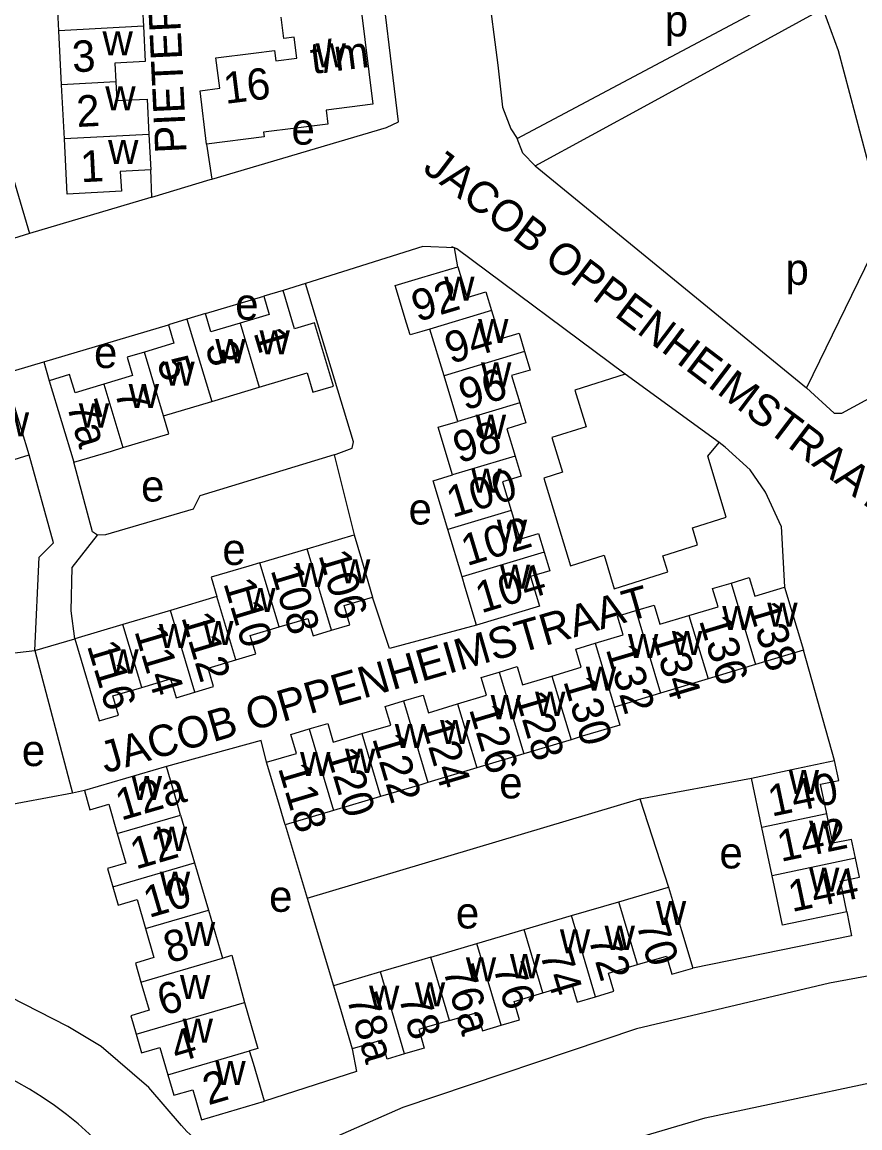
# Model space of a CAD drawing. Extents: x 157569 to 159501, y 382907 to 384670.
# Drawn here: x 158949.1 to 159055.8, y 383261.5 to 383402.3 of the extents above; entities that cross this region are included whole.
import ezdxf

# ---------------------------------------------------------------- set-up
doc = ezdxf.new("R2010")
doc.units = 0
for name, color, linetype in [('BLT_Basislijn', 7, 'Continuous'), ('BLT_Bebouwing', 7, 'Continuous'), ('BLT_Centroide', 7, 'Continuous'), ('BLT_Huisnummer', 7, 'Continuous'), ('BLT_Huisnummer_ tussenligend', 7, 'Continuous'), ('BLT_Huisnummer_reeks', 7, 'Continuous'), ('BLT_Onderverdeling_panden', 7, 'Continuous'), ('BLT_Straatnaam_verkleind', 7, 'Continuous')]:
    doc.layers.add(name, color=color, linetype=linetype)

msp = doc.modelspace()

# ---------------------------------------------------------------- linework, layer by layer
at = {"layer": 'BLT_Basislijn'}
for p, q in [((159014.42, 383384.03), (159028.76, 383391.86)), ((158972.61, 383386.8), (158973.27, 383382.34)), ((159014.42, 383384.03), (159049, 383355.73)), ((158965.65, 383380.05), (158965.49, 383383.53)), ((158950.05, 383375.4), (158944.99, 383373.86)), ((159004.61, 383371.17), (159004.15, 383373.58)), ((158985.21, 383369.05), (158982.34, 383368.14)), ((158972.45, 383365.2), (158979.89, 383367.41)), ((158951.86, 383359.07), (158967.74, 383363.79)), ((158946.3, 383357.42), (158951.86, 383359.07)), ((158951.86, 383359.07), (158952.57, 383356.65)), ((159037.86, 383348.77), (159025.91, 383357.49)), ((158988.85, 383347.23), (158991.38, 383337.03)), ((159045.74, 383338.12), (159046.18, 383330.34)), ((158950.73, 383322.27), (158955.82, 383323.75)), ((158947.42, 383321.92), (158950.73, 383322.27)), ((158950.73, 383322.27), (158955.52, 383304.09)), ((159052.56, 383308.26), (159048.59, 383322.32)), ((159027.77, 383303.39), (159041.99, 383306.03)), ((158955.52, 383304.09), (158943.57, 383301.89)), ((158957.04, 383304.44), (158955.52, 383304.09)), ((158985.41, 383290.74), (159027.77, 383303.39)), ((159027.77, 383303.39), (159031.43, 383292.15)), ((158982.62, 383300.07), (158985.41, 383290.74)), ((158985.41, 383290.74), (158988.75, 383279.57))]:
    msp.add_line(p, q, dxfattribs=at)
for points in [[(158941.85, 383428.43), (158943.35, 383398.06), (158950.05, 383375.4)], [(159012.14, 383387.53), (159050.09, 383407.72), (159049.75, 383410.1), (159047.73, 383417.9), (159045.92, 383423.74)], [(158973.27, 383382.34), (158995.52, 383388.93), (158997.04, 383389.62), (158994.36, 383411.78)], [(159007.74, 383411.49), (159008.38, 383407.02), (159009.67, 383396.84), (159010.29, 383391.5), (159011.35, 383388.75), (159012.14, 383387.53)], [(159028.76, 383391.86), (159050.35, 383403.64), (159051.14, 383403.8), (159053, 383398.73), (159058.78, 383376.99), (159058.82, 383375.95), (159049, 383355.73)], [(159014.42, 383384.03), (159012.86, 383385.63), (159012.14, 383387.53)], [(158965.65, 383380.05), (158973.07, 383382.28), (158973.27, 383382.34)], [(158965.65, 383380.05), (158965.49, 383380), (158950.05, 383375.4)], [(159004.15, 383373.58), (159000.13, 383373.74), (158985.21, 383369.05)], [(159004.15, 383373.58), (159003.82, 383373.72)], [(159025.91, 383357.49), (159004.47, 383373.44), (159004.15, 383373.58)], [(158988.85, 383347.23), (158989.12, 383347.31), (158991.13, 383348.05), (158991.29, 383348.85), (158985.21, 383369.05)], [(159025.91, 383357.49), (159019.49, 383355.46), (159020.91, 383350.8), (159016.56, 383349.42), (159017.9, 383345), (159015.54, 383344.25), (159018.93, 383333.08), (159023.2, 383334.43), (159024.5, 383330.15), (159031.32, 383332.31), (159030.7, 383334.35), (159035.12, 383335.75), (159034.47, 383337.91), (159038.77, 383339.27), (159036.41, 383347.04), (159037.86, 383348.77)], [(159049, 383355.73), (159052.52, 383352.54), (159053.48, 383352.51), (159057.95, 383354.93)], [(158983.24, 383235.61), (158982.98, 383236.31), (158981.28, 383239.26), (158981.31, 383241.77), (158983.04, 383243.59), (159007.41, 383254.28), (159036.07, 383262.73), (159100, 383276.35), (159146.03, 383286.21), (159155.39, 383288.52), (159181.52, 383295.52), (159205.36, 383303.77), (159241.92, 383319.57), (159301.34, 383349.43)], [(159045.74, 383338.12), (159043.77, 383342.46), (159041.82, 383345.29), (159038.64, 383348.2), (159037.86, 383348.77)], [(158950.73, 383322.27), (158951.29, 383334.17), (158953.11, 383336.02), (158950.02, 383347.21)], [(158988.85, 383347.23), (158971.76, 383341.99), (158970.9, 383340.27), (158959.73, 383337.01), (158958.71, 383336.98)], [(158958.71, 383336.98), (158958.09, 383337.42), (158955.69, 383346.26)], [(159258.99, 383340.92), (159227.33, 383325.46), (159190.02, 383310.81), (159165.47, 383303.18), (159141.61, 383297.45), (159119.64, 383292.64), (159100, 383288.81), (159051.92, 383279.92), (159027.35, 383274.07), (158997.57, 383264.08), (158986.46, 383259.17)], [(158955.82, 383323.75), (158955.38, 383327.35), (158955.47, 383332.86), (158958.71, 383336.98)], [(159006.98, 383325.53), (158995.91, 383322.55), (158993.74, 383329.1)], [(158980.25, 383308.06), (158979.54, 383310.8), (158967.49, 383307.49)], [(159054.12, 383289), (159054.7, 383285.92), (159034.49, 383281.82)], [(158969.39, 383261.76), (158965.23, 383266.61), (158959.2, 383271.82), (158954.92, 383274.37), (158947.54, 383278.14), (158941.39, 383279.86), (158939.55, 383280.38)], [(158962.81, 383255.07), (158961.61, 383256.56), (158960.36, 383257.99), (158959.05, 383259.37), (158957.67, 383260.7), (158956.25, 383261.97), (158954.77, 383263.17), (158953.24, 383264.32), (158951.67, 383265.39), (158950.06, 383266.4), (158948.4, 383267.35), (158946.7, 383268.22), (158944.97, 383269.02), (158943.21, 383269.74), (158941.42, 383270.4), (158939.6, 383270.97), (158938.1, 383271.39)], [(158991.13, 383271.52), (158991.68, 383268.66), (158979.96, 383264.86)], [(158969.39, 383261.76), (158970.1, 383261.01), (158970.86, 383260.32), (158971.67, 383259.69), (158972.53, 383259.13), (158973.43, 383258.63), (158974.37, 383258.21), (158975.34, 383257.86), (158976.33, 383257.59), (158977.34, 383257.39), (158978.36, 383257.27), (158979.39, 383257.24), (158980.41, 383257.28), (158981.43, 383257.4), (158982.44, 383257.6), (158983.43, 383257.88), (158984.48, 383258.27)]]:
    msp.add_lwpolyline(points, dxfattribs=at)
at = {"layer": 'BLT_Bebouwing'}
for p, q in [((158953.79, 383401.25), (158953.43, 383408.13)), ((158992.23, 383404.25), (158992.74, 383400.13)), ((158954.15, 383394.37), (158953.79, 383401.25)), ((158992.74, 383400.13), (158993.25, 383396)), ((158954.5, 383387.48), (158954.15, 383394.37)), ((158965.26, 383388.03), (158965.49, 383383.53)), ((158983.95, 383388.83), (158979.84, 383388.32)), ((158982.34, 383368.14), (158979.89, 383367.41)), ((158970.1, 383364.49), (158967.74, 383363.79)), ((158972.45, 383365.2), (158970.1, 383364.49)), ((159002.83, 383357.27), (159001.02, 383363.24)), ((159004.57, 383351.47), (159002.83, 383357.27)), ((158952.57, 383356.65), (158955.69, 383346.26)), ((158973.25, 383354.01), (158979.31, 383355.83)), ((158950.02, 383347.21), (158948.08, 383353.68)), ((158967.12, 383352.17), (158973.25, 383354.01)), ((159005.14, 383331.65), (159003.32, 383337.69)), ((158985.4, 383335.25), (158991.38, 383337.03)), ((158979.4, 383333.46), (158985.4, 383335.25)), ((159046.18, 383330.34), (159048.59, 383322.32)), ((158973.92, 383329.15), (158968, 383327.39)), ((158968, 383327.39), (158961.95, 383325.58)), ((158961.95, 383325.58), (158955.82, 383323.75)), ((159048.59, 383322.32), (159042.49, 383320.49)), ((159042.49, 383320.49), (159036.45, 383318.67)), ((159036.45, 383318.67), (159030.4, 383316.85)), ((159030.4, 383316.85), (159024.53, 383315.08)), ((159019.01, 383310.92), (159012.98, 383309.11)), ((159012.98, 383309.11), (159007, 383307.32)), ((158967.49, 383307.49), (158957.04, 383304.44)), ((159007, 383307.32), (159000.76, 383305.45)), ((159043.31, 383299.74), (159041.99, 383306.03)), ((158994.76, 383303.67), (158988.76, 383301.89)), ((158969.3, 383301.31), (158971.08, 383295.22)), ((158988.76, 383301.89), (158982.62, 383300.07)), ((159044.61, 383293.59), (159043.31, 383299.74)), ((158971.08, 383295.22), (158972.84, 383289.19)), ((159025.09, 383290.28), (159031.43, 383292.15)), ((159019.06, 383288.51), (159025.09, 383290.28)), ((158972.84, 383289.19), (158974.63, 383283.07)), ((159013.04, 383286.73), (159019.06, 383288.51)), ((159007, 383284.95), (159013.04, 383286.73)), ((159001.14, 383283.22), (159007, 383284.95)), ((158994.73, 383281.33), (158988.75, 383279.57)), ((158967.68, 383268.24), (158968.44, 383265.62)), ((158971.94, 383262.51), (158979.96, 383264.86))]:
    msp.add_line(p, q, dxfattribs=at)
for points in [[(158960.3, 383408.49), (158960.43, 383406.08), (158964.32, 383406.29), (158964.55, 383401.81)], [(158978.59, 383398.39), (158981.24, 383398.72), (158981.4, 383397.41), (158984.1, 383397.75), (158983.77, 383400.41), (158982.42, 383400.24), (158982.08, 383402.99)], [(158964.55, 383401.81), (158964.78, 383397.33), (158960.92, 383397.13), (158961.04, 383394.73)], [(158972.61, 383386.8), (158971.77, 383393.6), (158974.27, 383393.91), (158973.79, 383397.79), (158978.59, 383398.39)], [(158993.25, 383396), (158993.76, 383391.88), (158987.83, 383391.14)], [(158961.04, 383394.73), (158961.17, 383392.34), (158965.02, 383392.54), (158965.26, 383388.03)], [(158987.83, 383391.14), (158988.05, 383389.34), (158983.95, 383388.83)], [(158979.84, 383388.32), (158979.92, 383387.71), (158972.61, 383386.8)], [(158965.49, 383383.53), (158961.62, 383383.33), (158961.75, 383380.8), (158954.87, 383380.44), (158954.5, 383387.48)], [(159001.02, 383363.24), (159000, 383362.94), (158998.52, 383362.49), (158998.07, 383363.99), (158996.62, 383368.77), (159000, 383369.79), (159004.61, 383371.17)], [(159004.61, 383371.17), (159005.79, 383367.26), (159008.15, 383367.98), (159008.87, 383365.6)], [(158986.14, 383355.18), (158988.75, 383355.96), (158986.33, 383364.02), (158983.8, 383363.26), (158982.34, 383368.14)], [(158979.89, 383367.41), (158980.58, 383365.11), (158976.86, 383363.99)], [(159008.87, 383365.6), (159009.96, 383361.99), (159012.38, 383362.72), (159013.09, 383360.37)], [(158976.86, 383363.99), (158973.15, 383362.88), (158972.45, 383365.2)], [(158967.74, 383363.79), (158968.45, 383361.43), (158964.68, 383360.3)], [(158964.68, 383360.3), (158962.5, 383359.64), (158963.19, 383357.32), (158959.52, 383356.22)], [(159013.09, 383360.37), (159013.8, 383358.02), (159011.43, 383357.3), (159012.47, 383353.85)], [(158959.52, 383356.22), (158955.85, 383355.12), (158955.15, 383357.43), (158952.57, 383356.65)], [(158979.31, 383355.83), (158985.39, 383357.66), (158986.14, 383355.18)], [(159012.47, 383353.85), (159013.24, 383351.27), (159010.82, 383350.54), (159011.87, 383347.06)], [(158961.95, 383348.13), (158967.8, 383349.89), (158967.12, 383352.17)], [(159003.91, 383344.66), (159002.08, 383350.72), (159004.57, 383351.47)], [(158944.19, 383345.45), (158945.03, 383345.7), (158950.02, 383347.21)], [(158955.69, 383346.26), (158960.48, 383347.69), (158961.95, 383348.13)], [(159011.87, 383347.06), (159012.64, 383344.5), (159010.28, 383343.79), (159011.39, 383340.12)], [(159003.32, 383337.69), (159001.44, 383343.92), (159003.91, 383344.66)], [(159011.39, 383340.12), (159012.49, 383336.46), (159014.87, 383337.17), (159015.58, 383334.8)], [(158991.38, 383337.03), (158992.31, 383333.89), (158993.74, 383329.1)], [(159015.58, 383334.8), (159016.29, 383332.44), (159013.83, 383331.7), (159014.97, 383327.94), (159006.98, 383325.53)], [(158979.4, 383333.46), (158977.98, 383333.04), (158973.19, 383331.61), (158973.92, 383329.15)], [(159006.98, 383325.53), (159005.54, 383330.32), (159005.14, 383331.65)], [(159039.37, 383330.87), (159041.7, 383331.57), (159042.41, 383329.2), (159046.18, 383330.34)], [(159034.02, 383326.74), (159037.73, 383327.86), (159037.03, 383330.17), (159039.37, 383330.87)], [(158988.5, 383324.86), (158990.84, 383325.55), (158990.11, 383328.01), (158993.74, 383329.1)], [(159022.09, 383323.2), (159025.63, 383324.26), (159024.91, 383326.66), (159027.24, 383327.36)], [(159027.24, 383327.36), (159029.57, 383328.06), (159030.31, 383325.63), (159034.02, 383326.74)], [(158981.84, 383325.28), (158985.5, 383326.38), (158986.17, 383324.16), (158988.5, 383324.86)], [(158976.32, 383321.11), (158978.87, 383321.87), (158978.17, 383324.19), (158981.84, 383325.28)], [(158955.82, 383323.75), (158958.93, 383313.32), (158961.4, 383314.06), (158960.67, 383316.5), (158964.34, 383317.59)], [(159016.57, 383319.02), (159020.3, 383320.15), (159019.61, 383322.45), (159022.09, 383323.2)], [(158971.11, 383316.99), (158973.49, 383317.7), (158972.79, 383320.05), (158976.32, 383321.11)], [(159004.54, 383315.47), (159008.23, 383316.58), (159007.55, 383318.85), (159009.84, 383319.54)], [(159009.84, 383319.54), (159012.13, 383320.23), (159012.83, 383317.9), (159016.57, 383319.02)], [(158964.34, 383317.59), (158968, 383318.69), (158968.72, 383316.27), (158971.11, 383316.99)], [(158997.66, 383315.86), (159000.01, 383316.56), (159000.18, 383316.61), (159000.86, 383314.36), (159004.54, 383315.47)], [(158992.38, 383311.69), (158996.04, 383312.78), (158995.33, 383315.17), (158997.66, 383315.86)], [(159024.53, 383315.08), (159025.22, 383312.79), (159020.43, 383311.35), (159019.01, 383310.92)], [(158980.25, 383308.06), (158984.03, 383309.18), (158983.32, 383311.59), (158985.67, 383312.29)], [(158985.67, 383312.29), (158988.02, 383312.98), (158988.73, 383310.61), (158992.38, 383311.69)], [(158982.62, 383300.07), (158981.67, 383303.28), (158980.25, 383308.06)], [(159041.99, 383306.03), (159047.7, 383307.24), (159052.56, 383308.26)], [(159051.55, 383301.48), (159050.76, 383305.24), (159053.1, 383305.73), (159052.56, 383308.26)], [(158969.3, 383301.31), (158968.89, 383302.69), (158967.49, 383307.49)], [(159000.76, 383305.45), (159000, 383305.22), (158994.76, 383303.67)], [(158957.04, 383304.44), (158957.75, 383301.99), (158960.14, 383302.69), (158961.23, 383298.95)], [(159055.21, 383295.82), (159054.7, 383298.22), (159052.34, 383297.72), (159051.55, 383301.48)], [(158961.23, 383298.95), (158962.32, 383295.21), (158959.98, 383294.53), (158960.66, 383292.18)], [(159054.12, 383289), (159053.29, 383292.91), (159055.71, 383293.42), (159055.21, 383295.82)], [(159054.12, 383289), (159045.93, 383287.28), (159044.9, 383292.17), (159044.61, 383293.59)], [(158960.66, 383292.18), (158961.35, 383289.84), (158963.75, 383290.54), (158964.83, 383286.85)], [(159031.43, 383292.15), (159033.07, 383286.61), (159034.49, 383281.82)], [(158964.83, 383286.85), (158965.9, 383283.16), (158963.54, 383282.47), (158964.25, 383280.03)], [(158974.63, 383283.07), (158975.81, 383283.49), (158977.43, 383277.42)], [(159001.14, 383283.22), (159000, 383282.89), (158994.73, 383281.33)], [(159022.12, 383278.18), (159024.47, 383278.88), (159023.78, 383281.18), (159027.46, 383282.27)], [(159027.46, 383282.27), (159031.14, 383283.36), (159031.83, 383281.03), (159034.49, 383281.82)], [(158964.25, 383280.03), (158965.3, 383276.45), (158962.95, 383275.76), (158963.64, 383273.39)], [(158988.75, 383279.57), (158989.72, 383276.31), (158991.13, 383271.52)], [(159015.43, 383278.67), (159019.11, 383279.76), (159019.78, 383277.49), (159022.12, 383278.18)], [(159010.09, 383274.53), (159012.45, 383275.23), (159011.75, 383277.58), (159015.43, 383278.67)], [(158977.43, 383277.42), (158979.14, 383271.58), (158978.08, 383271.28)], [(159003.52, 383275.15), (159007.03, 383276.18), (159007.73, 383273.83), (159010.09, 383274.53)], [(159003.52, 383275.15), (159000, 383274.11), (158999.61, 383274), (159000, 383272.68), (159000.31, 383271.64), (159000, 383271.53), (158997.8, 383270.89)], [(158963.64, 383273.39), (158964.33, 383271.03), (158966.66, 383271.71), (158967.68, 383268.24)], [(158997.8, 383270.89), (158995.6, 383270.24), (158994.9, 383272.62), (158991.13, 383271.52)], [(158979.96, 383264.86), (158978.56, 383269.66), (158978.08, 383271.28)], [(158968.44, 383265.62), (158970.83, 383266.32), (158971.94, 383262.51)]]:
    msp.add_lwpolyline(points, dxfattribs=at)
at = {"layer": 'BLT_Onderverdeling_panden'}
for p, q in [((158964.55, 383401.81), (158953.79, 383401.25)), ((158961.04, 383394.73), (158954.15, 383394.37)), ((158965.26, 383388.03), (158954.5, 383387.48)), ((159008.87, 383365.6), (159001.02, 383363.24)), ((158970.1, 383364.49), (158973.25, 383354.01)), ((158976.86, 383363.99), (158979.31, 383355.83)), ((158967.12, 383352.17), (158964.68, 383360.3)), ((159013.09, 383360.37), (159002.83, 383357.27)), ((158959.52, 383356.22), (158961.95, 383348.13)), ((159012.47, 383353.85), (159004.57, 383351.47)), ((159011.87, 383347.06), (159003.91, 383344.66)), ((159011.39, 383340.12), (159003.32, 383337.69)), ((158988.5, 383324.86), (158985.4, 383335.25)), ((159015.58, 383334.8), (159005.14, 383331.65)), ((158981.84, 383325.28), (158979.4, 383333.46)), ((159039.37, 383330.87), (159042.49, 383320.49)), ((158976.32, 383321.11), (158973.92, 383329.15)), ((158971.11, 383316.99), (158968, 383327.39)), ((159027.24, 383327.36), (159030.4, 383316.85)), ((159034.02, 383326.74), (159036.45, 383318.67)), ((158964.34, 383317.59), (158961.95, 383325.58)), ((159022.09, 383323.2), (159024.53, 383315.08)), ((159009.84, 383319.54), (159012.98, 383309.11)), ((159016.57, 383319.02), (159019.01, 383310.92)), ((158997.66, 383315.86), (159000.76, 383305.45)), ((159004.54, 383315.47), (159007, 383307.32)), ((158985.67, 383312.29), (158988.76, 383301.89)), ((158992.38, 383311.69), (158994.76, 383303.67)), ((158961.23, 383298.95), (158969.3, 383301.31)), ((159051.55, 383301.48), (159043.31, 383299.74)), ((158960.66, 383292.18), (158971.08, 383295.22)), ((159055.21, 383295.82), (159044.61, 383293.59)), ((159027.46, 383282.27), (159025.09, 383290.28)), ((158964.83, 383286.85), (158972.84, 383289.19)), ((159022.12, 383278.18), (159019.06, 383288.51)), ((159015.43, 383278.67), (159013.04, 383286.73)), ((159010.09, 383274.53), (159007, 383284.95)), ((158964.25, 383280.03), (158974.63, 383283.07)), ((159003.52, 383275.15), (159001.14, 383283.22)), ((158997.8, 383270.89), (158994.73, 383281.33)), ((158963.64, 383273.39), (158977.43, 383277.42)), ((158967.68, 383268.24), (158978.08, 383271.28))]:
    msp.add_line(p, q, dxfattribs=at)

# ---------------------------------------------------------------- texts
at = {"layer": 'BLT_Centroide'}
for s, p in [('p', (159030.93, 383400.52)), ('w', (158959.35, 383398.09)), ('w', (158986.48, 383396.57)), ('w', (158959.7, 383391.09)), ('e', (158983.41, 383386.73)), ('w', (158960.06, 383384.25)), ('p', (159046.3, 383368.87)), ('w', (159002.85, 383366.84)), ('e', (158976.25, 383364.43)), ('w', (159007.16, 383361.44)), ('w', (158979.34, 383360)), ('e', (158958.27, 383358.27)), ('w', (158973.71, 383358.89)), ('w', (158967.22, 383356.02)), ('w', (159007.54, 383355.91)), ('w', (158962.68, 383353.17)), ('w', (158956.34, 383350.69)), ('w', (158946.14, 383349.56)), ('w', (159006.87, 383349.25)), ('e', (158964.26, 383341.26)), ('w', (159006.3, 383342.38)), ('e', (158998.32, 383338.33)), ('w', (159009.55, 383335.88)), ('e', (158974.61, 383333.18)), ('w', (158983.95, 383330.36)), ('w', (158989.58, 383330.84)), ('w', (159009.94, 383330.16)), ('w', (158977.52, 383327.19)), ('w', (159038.25, 383324.88)), ('w', (159043.98, 383325.31)), ('w', (158972.16, 383322.97)), ('w', (158966.53, 383322.59)), ('w', (159031.84, 383321.69)), ('w', (159026.25, 383321.33)), ('w', (158960.08, 383319.34)), ('w', (159020.89, 383317.17)), ('w', (159008.77, 383313.53)), ('w', (159014.42, 383313.95)), ('w', (159002.33, 383310.36)), ('w', (158996.56, 383309.86)), ('e', (158949.08, 383307.56)), ('w', (158984.5, 383306.28)), ('w', (158990.22, 383306.69)), ('w', (158963.06, 383303.22)), ('e', (159009.86, 383303.44)), ('w', (159046.71, 383304)), ('w', (159049.31, 383297.53)), ('w', (158966.25, 383296.75)), ('e', (159037.89, 383294.52)), ('w', (158966.65, 383291.03)), ('w', (159049.3, 383291.56)), ('e', (158980.56, 383288.99)), ('e', (159004.34, 383286.87)), ('w', (159029.8, 383287.31)), ('w', (158969.83, 383284.62)), ('w', (159017.58, 383283.69)), ('w', (159023.27, 383284.14)), ('w', (159005.61, 383280.14)), ('w', (159011.22, 383280.53)), ('w', (158969.21, 383277.88)), ('w', (158993.28, 383276.53)), ('w', (158999.12, 383276.95)), ('w', (158969.55, 383272.31)), ('w', (158973.71, 383266.91))]:
    msp.add_text(s, height=4, dxfattribs=at).set_placement(p)
at = {"layer": 'BLT_Huisnummer'}
for s, rotation, p in [('3', 2.9712, (158955.57, 383395.94)), ('2', 2.9712, (158956.12, 383388.97)), ('1', 2.9712, (158956.62, 383381.93)), ('92', 16.7776, (158999.43, 383364.12)), ('1', 286.7121, (158978.55, 383362.79)), ('5', 286.7167, (158966.25, 383359.14)), ('96', 16.7776, (159005.46, 383352.84)), ('7a', 286.7169, (158954.75, 383353.54)), ('100', 16.7776, (159003.89, 383339.17)), ('106', 286.6124, (158986.82, 383334.46)), ('104', 16.7776, (159007.56, 383327)), ('110', 286.6124, (158974.71, 383330.88)), ('138', 286.7517, (159041.55, 383327.88)), ('134', 286.7517, (159029.23, 383324.23)), ('116', 286.6124, (158957.35, 383322.91)), ('130', 286.5256, (159017.99, 383318.4)), ('126', 286.5256, (159005.99, 383314.82)), ('122', 286.5256, (158993.66, 383311.11)), ('118', 286.5256, (158981.67, 383307.33)), ('140', 11.8824, (159044.54, 383301.1)), ('12a', 16.2937, (158961.71, 383300.59)), ('10', 16.2931, (158965.26, 383288.19)), ('144', 11.8824, (159047.12, 383288.95)), ('70', 286.5183, (159027.27, 383287.47)), ('74', 286.5183, (159015.01, 383283.68)), ('76a', 286.4014, (159002.67, 383281.6)), ('6', 16.2931, (158967.02, 383275.72)), ('78a', 286.4018, (158990.4, 383278.02)), ('2', 16.2931, (158972.81, 383264.33))]:
    msp.add_text(s, height=4, rotation=rotation, dxfattribs=at).set_placement(p)
at = {"layer": 'BLT_Huisnummer_ tussenligend'}
for s, rotation, p in [('94', 16.7776, (159003.67, 383358.77)), ('3', 286.7121, (158972.38, 383361.04)), ('7', 286.7155, (158960.86, 383355.24)), ('98', 16.7776, (159004.72, 383346.11)), ('102', 16.7776, (159005.74, 383333.02)), ('108', 286.6124, (158980.73, 383332.55)), ('112', 286.6124, (158969.36, 383326.54)), ('136', 286.7517, (159035.27, 383326.13)), ('114', 286.6124, (158963.38, 383324.77)), ('132', 286.5256, (159023.4, 383322.47)), ('128', 286.5256, (159011.86, 383316.48)), ('124', 286.5256, (158999.93, 383312.97)), ('120', 286.5256, (158987.8, 383309.29)), ('142', 11.8824, (159045.71, 383295.34)), ('12', 16.2931, (158963.58, 383294.36)), ('8', 16.2931, (158967.83, 383282.4)), ('72', 286.5183, (159021.18, 383285.61)), ('76', 286.5183, (159009.05, 383281.93)), ('78', 286.4018, (158997.02, 383278.11)), ('4', 16.2931, (158968.77, 383269.73))]:
    msp.add_text(s, height=4, rotation=rotation, dxfattribs=at).set_placement(p)
at = {"layer": 'BLT_Huisnummer_reeks'}
for s, rotation, p in [('t/m', 7.0846, (158986.08, 383395.72)), ('16', 7.0922, (158975, 383391.91))]:
    msp.add_text(s, height=4, rotation=rotation, dxfattribs=at).set_placement(p)
at = {"layer": 'BLT_Straatnaam_verkleind'}
for s, rotation, p in [('PIETER OUDHOF', 92.7263, (158970.07, 383385.72)), ('JACOB OPPENHEIMSTRAAT', 322.9024, (158999.97, 383383.43)), ('JACOB OPPENHEIMSTRAAT', 16.1852, (158959.71, 383306.61))]:
    msp.add_text(s, height=4, rotation=rotation, dxfattribs=at).set_placement(p)

doc.saveas('drawing.dxf')
